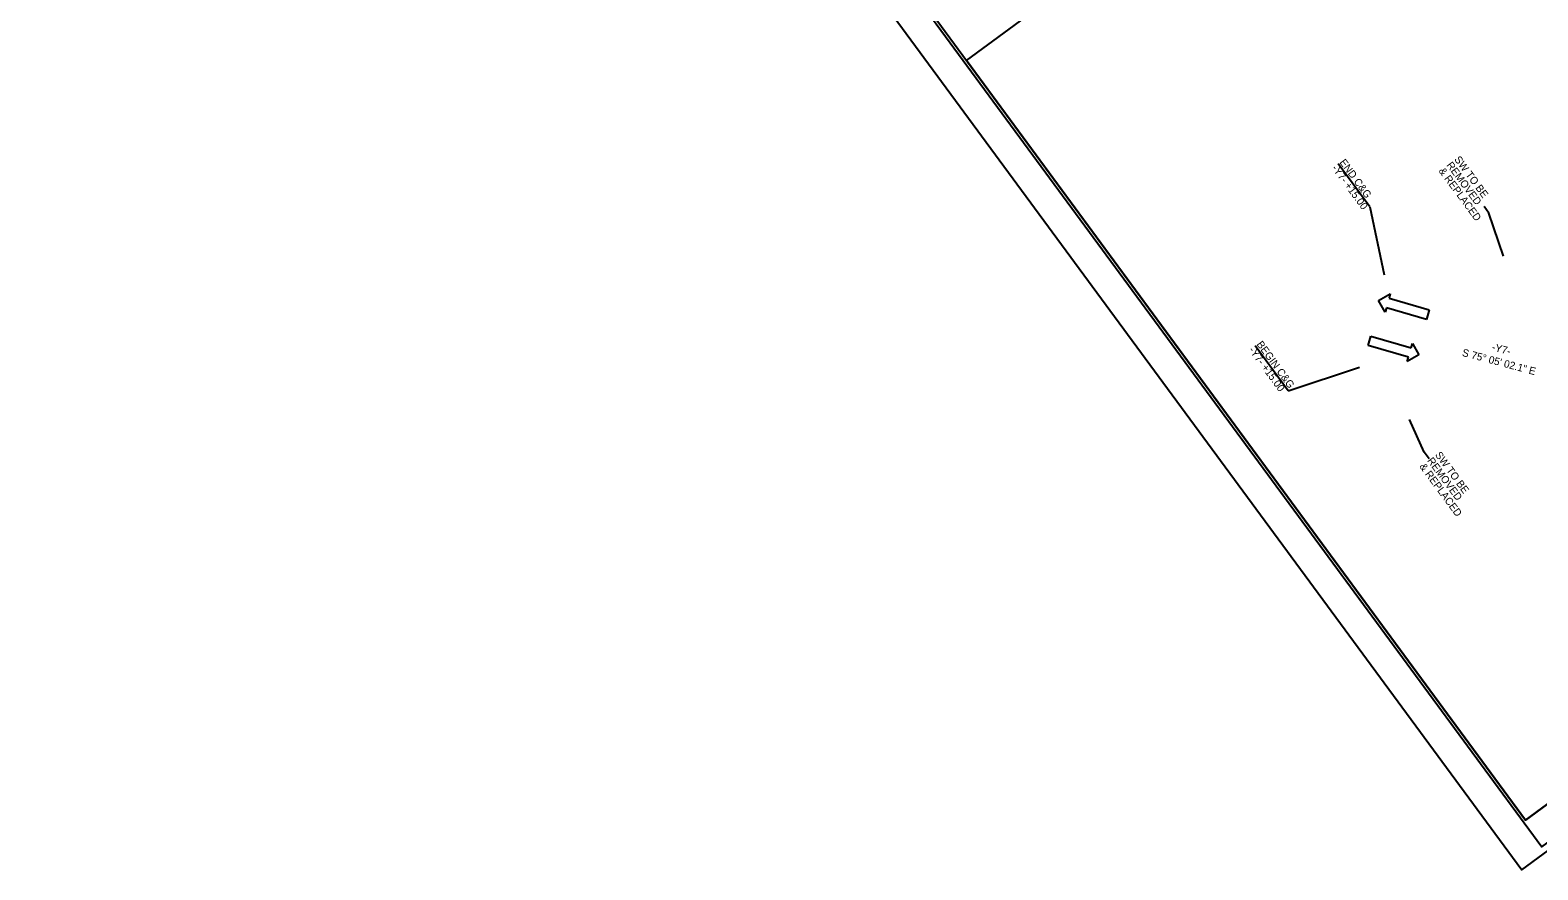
# Model space of a CAD drawing. Extents: x 1763480 to 1764420, y 711010 to 712012.
# Drawn here: x 1763480 to 1763984, y 711010 to 711291 of the extents above; entities that cross this region are included whole.
import ezdxf

# ---------------------------------------------------------------- set-up
doc = ezdxf.new("R2010")
doc.units = 0
for name, color, linetype in [('P-WATER', 7, 'Continuous'), ('Prop Conc 4in Sidewalk', 7, 'Continuous'), ('Prop Grid Mask', 7, 'Continuous'), ('Prop Horizontal Alignment Direction Label', 7, 'Continuous'), ('Prop Horizontal Alignment Station Label', 7, 'Continuous'), ('Prop Lane Arrow CELL', 7, 'Continuous'), ('Sheet Plot Border Inside CELL', 7, 'Continuous'), ('Sheet Plot Border Outside CELL', 7, 'Continuous')]:
    doc.layers.add(name, color=color, linetype=linetype)

msp = doc.modelspace()

# ---------------------------------------------------------------- linework, layer by layer
at = {"layer": 'P-WATER'}
msp.add_lwpolyline([(1764402.04, 711336.79), (1763957.77, 711941.04), (1763535.55, 711630.61), (1763979.82, 711026.35)], close=True, dxfattribs=at)
at = {"layer": 'Prop Conc 4in Sidewalk'}
for p, q in [((1763967.57, 711229.4), (1763965.95, 711231.6)), ((1763972.42, 711215.07), (1763967.57, 711229.4)), ((1763945.95, 711149.4), (1763941.05, 711160.37)), ((1763947.57, 711147.21), (1763945.95, 711149.4))]:
    msp.add_line(p, q, dxfattribs=at)
at = {"layer": 'Prop Grid Mask'}
for p, q in [((1763927.74, 711231.59), (1763917.16, 711245.94)), ((1763927.74, 711231.59), (1763932.48, 711208.83)), ((1763900.46, 711169.94), (1763889.37, 711185.08)), ((1763900.46, 711169.94), (1763924.24, 711177.91))]:
    msp.add_line(p, q, dxfattribs=at)
at = {"layer": 'Prop Horizontal Alignment Station Label'}
msp.add_lwpolyline([(1763957.77, 711941.04), (1764052.94, 711811.6), (1764008.24, 711778.74), (1764295.85, 711387.56), (1764241.65, 711347.71), (1764301.88, 711263.14), (1763979.82, 711026.35), (1763792.92, 711280.55), (1763982.56, 711419.98), (1763871.46, 711571.1), (1763681.82, 711431.66), (1763535.55, 711630.61)], close=True, dxfattribs=at)
at = {"layer": 'Prop Lane Arrow CELL'}
for p, q in [((1763930.67, 711200.18), (1763934.59, 711202.38)), ((1763934.59, 711202.38), (1763934.17, 711200.94)), ((1763934.17, 711200.94), (1763947.62, 711197.06)), ((1763932.84, 711196.33), (1763930.67, 711200.18)), ((1763933.26, 711197.77), (1763932.84, 711196.33)), ((1763946.71, 711193.89), (1763933.26, 711197.77)), ((1763947.62, 711197.06), (1763946.71, 711193.89)), ((1763927.19, 711185.11), (1763928.1, 711188.28)), ((1763940.64, 711181.23), (1763927.19, 711185.11)), ((1763928.1, 711188.28), (1763941.55, 711184.4)), ((1763941.55, 711184.4), (1763941.97, 711185.84)), ((1763941.97, 711185.84), (1763944.14, 711181.99)), ((1763944.14, 711181.99), (1763940.22, 711179.79)), ((1763940.22, 711179.79), (1763940.64, 711181.23))]:
    msp.add_line(p, q, dxfattribs=at)
at = {"layer": 'Sheet Plot Border Inside CELL'}
msp.add_lwpolyline([(1763491.78, 711688.55), (1763985.22, 711017.43), (1764410.21, 711329.9), (1763916.77, 712001.02)], close=True, dxfattribs=at)
at = {"layer": 'Sheet Plot Border Outside CELL'}
msp.add_lwpolyline([(1763479.87, 711687.86), (1763978.5, 711009.69), (1764419.6, 711334.01), (1763920.98, 712012.18)], close=True, dxfattribs=at)

# ---------------------------------------------------------------- texts
at = {"layer": 'Prop Conc 4in Sidewalk'}
for s, p in [('REMOVED', (1763953.24, 711245.47)), ('SW TO BE', (1763955.85, 711247.4)), ('& REPLACED', (1763950.62, 711243.54)), ('& REPLACED', (1763944.18, 711144.65)), ('REMOVED', (1763946.79, 711146.58)), ('SW TO BE', (1763949.41, 711148.5))]:
    msp.add_text(s, height=2.5, rotation=306.3875, dxfattribs=at).set_placement(p)
at = {"layer": 'Prop Grid Mask'}
for s, rotation, p in [('END C&G', 306.3875, (1763917.47, 711246.4)), ('-Y7- +15.00', 306.3875, (1763914.85, 711244.47)), ('BEGIN C&G', 306.2176, (1763889.74, 711185.53)), ('-Y7- +15.00', 306.2176, (1763887.12, 711183.61))]:
    msp.add_text(s, height=2.5, rotation=rotation, dxfattribs=at).set_placement(p)
at = {"layer": 'Prop Horizontal Alignment Direction Label'}
for s, p in [('-Y7-', (1763968.35, 711183.56)), ('S 75%%d 05\' 02.1" E', (1763958.4, 711181.7))]:
    msp.add_text(s, height=2.5, rotation=345.0839, dxfattribs=at).set_placement(p)

doc.saveas('drawing.dxf')
